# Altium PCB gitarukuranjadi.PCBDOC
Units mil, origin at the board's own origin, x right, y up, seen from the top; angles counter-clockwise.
Board outline 9670 x 5425 mil, 2 copper layers (Top Layer, Bottom Layer); 62 components, 44 nets, 204 pads, 7 vias.
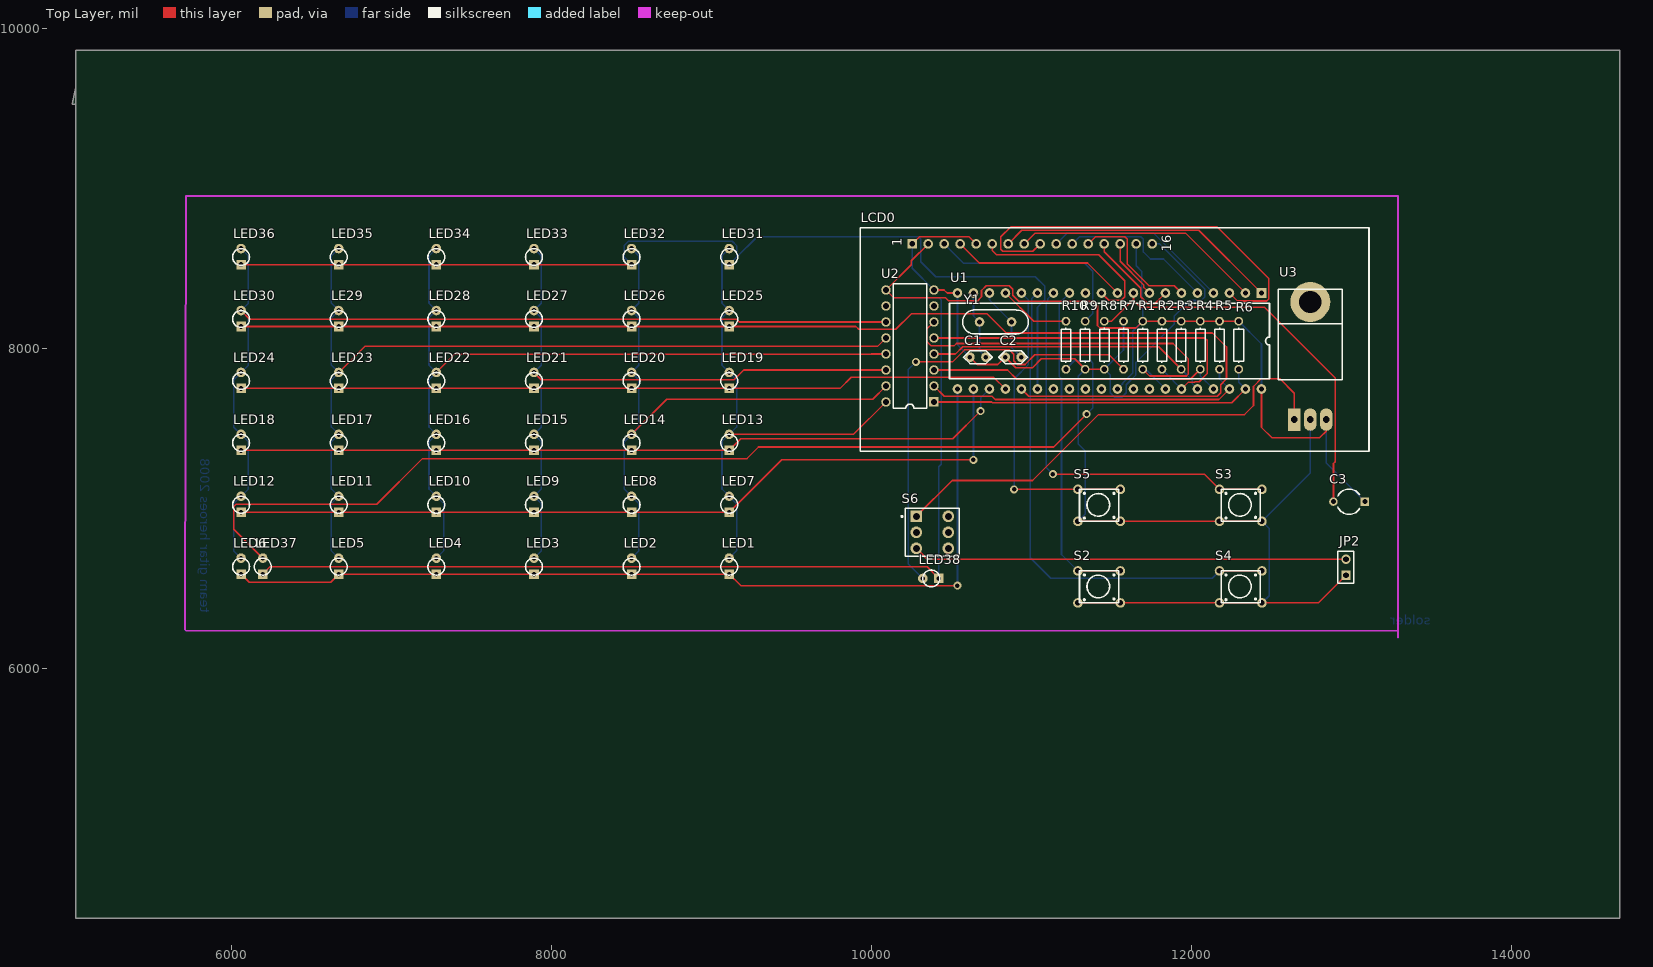
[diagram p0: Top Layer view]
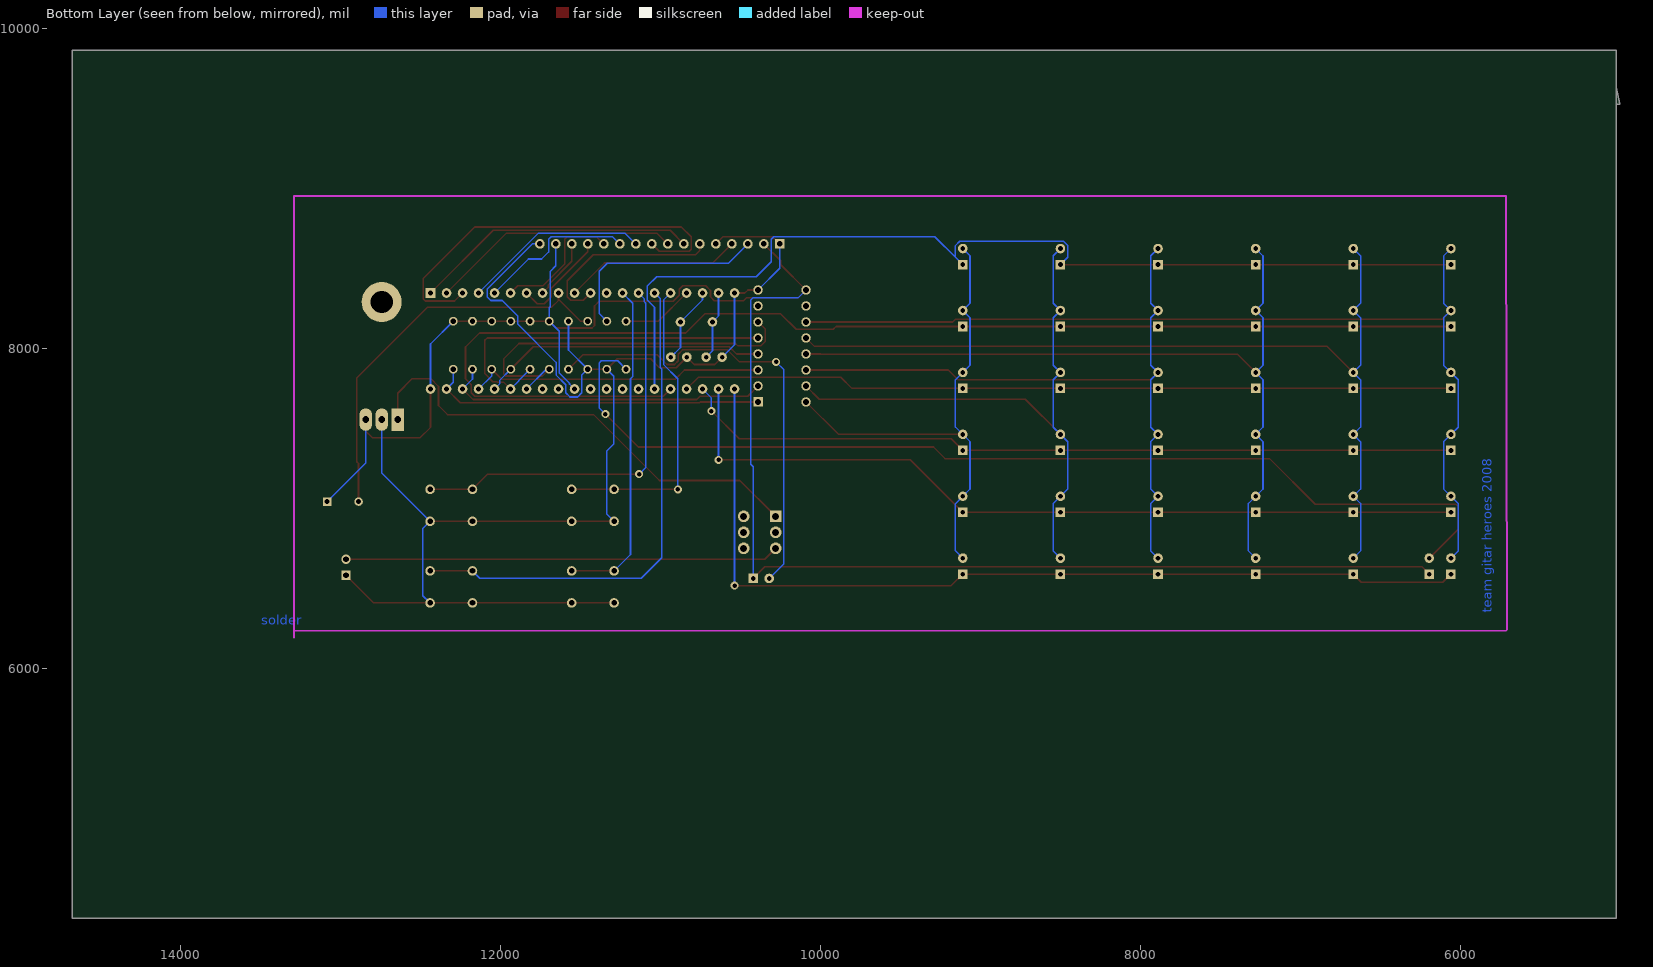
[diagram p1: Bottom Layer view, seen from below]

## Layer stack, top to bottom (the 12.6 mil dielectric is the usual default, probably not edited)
Top Layer: signal copper 1.4
Dielectric: dielectric 12.6, FR-4, Dk 4.8
Bottom Layer: signal copper 1.4

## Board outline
5025,9630 5025,4435 14675,4435 14675,9860 5025,9860 5025,9525 5005,9525

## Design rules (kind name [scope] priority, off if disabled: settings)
Clearance [All] p1: gap=10
ComponentClearance [All] p1: gap=10 collisioncheckmode=0
PolygonConnect [All] p1: connectstyle=Relief reliefconductorwidth=10 reliefentries=4 polygonreliefangle="90 Angle"
RoomDefinition gitarukuranjadi [InComponentClass('gitarukuranjadi')] p1: confinementstyle=ConfineIn formatcopy=TRUE outline 0,0 2000,0 2000,1000 0,1000
RoutingLayers [All] p1: top layer=Horizontal bottom layer=Vertical
RoutingVias [All] p1: holewidth=28 width=50 viastyle="Through Hole" minholewidth=28 minwidth=50 maxholewidth=28 maxwidth=50
SolderMaskExpansion [All] p1: expansion=4
TestPointUsage [All] p1: valid=0 allowmultiple=FALSE
Testpoint [All] p1: side=15 testpointundercomponent=TRUE minsize=40 maxsize=100 preferedsize=60 minholesize=0 maxholesize=40 preferedholesize=32 testpointgrid=1 style=1023 order=1234567890
Width [All] p1: maxlimit=10 minlimit=10 preferedwidth=10
16 further rules are at their usual default settings.

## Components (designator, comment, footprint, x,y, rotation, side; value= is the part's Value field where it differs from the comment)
C1 "cap 33pF" "cap 22/33uF" 11014.63,7942.72 r180 top
C2 "cap 33pF" "cap 22/33uF" 11234.63,7942.72 r180 top
C3 "Cap2" CAPR5-4X5 12985.02,7039.84 r180 top
JP2 "Header 2" HDR1X2 12965.02,6579.84 r90 top
LCD0 "LCD 16X2" "LCD 16X2" 12854.63,10807.72 r90 top
LE29 "LED kecil" "LED kecil" 6569.39,8234.27 r90 top
LED1 "LED kecil" "LED kecil" 9010.08,6686.3 r90 top
LED2 "LED kecil" "LED kecil" 8399.91,6686.3 r90 top
LED3 "LED kecil" "LED kecil" 7789.73,6686.3 r90 top
LED4 "LED kecil" "LED kecil" 7179.56,6686.3 r90 top
LED5 "LED kecil" "LED kecil" 6569.39,6686.3 r90 top
LED6 "LED kecil" "LED kecil" 5959.21,6686.3 r90 top
LED7 "LED kecil" "LED kecil" 9010.08,7073.29 r90 top
LED8 "LED kecil" "LED kecil" 8399.91,7073.29 r90 top
LED9 "LED kecil" "LED kecil" 7789.73,7073.29 r90 top
LED10 "LED kecil" "LED kecil" 7179.56,7073.29 r90 top
LED11 "LED kecil" "LED kecil" 6569.39,7073.29 r90 top
LED12 "LED kecil" "LED kecil" 5959.21,7073.29 r90 top
LED13 "LED kecil" "LED kecil" 9010.08,7460.28 r90 top
LED14 "LED kecil" "LED kecil" 8399.91,7460.28 r90 top
LED15 "LED kecil" "LED kecil" 7789.73,7460.28 r90 top
LED16 "LED kecil" "LED kecil" 7179.56,7460.28 r90 top
LED17 "LED kecil" "LED kecil" 6569.39,7460.28 r90 top
LED18 "LED kecil" "LED kecil" 5959.21,7460.28 r90 top
LED19 "LED kecil" "LED kecil" 9010.08,7847.28 r90 top
LED20 "LED kecil" "LED kecil" 8399.91,7847.28 r90 top
LED21 "LED kecil" "LED kecil" 7789.73,7847.28 r90 top
LED22 "LED kecil" "LED kecil" 7179.56,7847.28 r90 top
LED23 "LED kecil" "LED kecil" 6569.39,7847.28 r90 top
LED24 "LED kecil" "LED kecil" 5959.21,7847.28 r90 top
LED25 "LED kecil" "LED kecil" 9010.08,8234.27 r90 top
LED26 "LED kecil" "LED kecil" 8399.91,8234.27 r90 top
LED27 "LED kecil" "LED kecil" 7789.73,8234.27 r90 top
LED28 "LED kecil" "LED kecil" 7179.56,8234.27 r90 top
LED30 "LED kecil" "LED kecil" 5959.21,8234.27 r90 top
LED31 "LED kecil" "LED kecil" 9010.08,8621.26 r90 top
LED32 "LED kecil" "LED kecil" 8399.91,8621.26 r90 top
LED33 "LED kecil" "LED kecil" 7789.73,8621.26 r90 top
LED34 "LED kecil" "LED kecil" 7179.56,8621.26 r90 top
LED35 "LED kecil" "LED kecil" 6569.39,8621.26 r90 top
LED36 "LED kecil" "LED kecil" 5959.21,8621.26 r90 top
LED37 "LED kecil" "LED kecil" 6094.89,6686.3 r90 top
LED38 "LED kecil" "LED kecil" 10320,6460 r180 top
R1 "Res1" AXIAL-0.3 11694.63,8017.72 r270 top
R2 "Res1" AXIAL-0.3 11814.63,8017.72 r270 top
R3 "Res1" AXIAL-0.3 11934.63,8017.72 r270 top
R4 "Res1" AXIAL-0.3 12054.63,8017.72 r270 top
R5 "Res1" AXIAL-0.3 12174.63,8017.72 r270 top
R6 "Res1" AXIAL-0.3 12294.63,8017.72 r270 top
R7 "Res1" AXIAL-0.3 11574.63,8017.72 r270 top
R8 "Res1" AXIAL-0.3 11454.63,8017.72 r270 top
R9 "Res1" AXIAL-0.3 11334.63,8017.72 r270 top
R10 "Res1" AXIAL-0.3 11214.63,8017.72 r270 top
S2 "pushbutton" pushbutton 11854.63,6507.72 r0 top
S3 "pushbutton" pushbutton 12739.63,7017.72 r0 top
S4 "pushbutton" pushbutton 12739.63,6507.72 r0 top
S5 "pushbutton" pushbutton 11854.63,7017.72 r0 top
S6 "SW-DPDT" DPDT-6 10379.63,6847.72 r0 top
U1 "8051" "8051 40 pin" 10734.63,6597.72 r270 top
U2 "ULN2003A" A16 10239.63,8012.72 r90 top
U3 "7805" 78XX/79XX 12259.63,7792.72 r90 top
Y1 "XTAL" XTAL 10774.63,8062.72 r0 top

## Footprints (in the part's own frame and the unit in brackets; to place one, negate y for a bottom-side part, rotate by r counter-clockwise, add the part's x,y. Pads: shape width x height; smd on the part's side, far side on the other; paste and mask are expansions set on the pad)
78XX/79XX [mil]
  round 250 hole 140: 0(495,-482)
  rect 140x80 hole 42: 1(-240,-382)
  oval 140x80 hole 42: 2(-240,-482) 3(-240,-582)
  silkscreen extent 10,-682 575,-282
"8051 40 pin" [mil]
  rect 60x60 hole 33: 1(-1746,1702)
  round 60 hole 33: 2(-1746,1602) 3(-1746,1502) 4(-1746,1402) 5(-1746,1302) 6(-1746,1202) 7(-1746,1102) 8(-1746,1002) 9(-1746,902) 10(-1746,802) 11(-1746,702) 12(-1746,602) 13(-1746,502) 14(-1746,402) 15(-1746,302) 16(-1746,202) 17(-1746,102) 18(-1746,2) 19(-1746,-98) 20(-1746,-198) 21(-1146,-198) 22(-1146,-98) 23(-1146,2) 24(-1146,102) 25(-1146,202) 26(-1146,302) 27(-1146,402) 28(-1146,502) 29(-1146,602) 30(-1146,702) 31(-1146,802) 32(-1146,902) 33(-1146,1002) 34(-1146,1102) 35(-1146,1202) 36(-1146,1302) 37(-1146,1402) 38(-1146,1502) 39(-1146,1602) 40(-1146,1702)
  silkscreen extent -1681,-248 -1211,1752
A16 [mm] "DIP; 16 Leads; Row Spacing 7.62 mm; Pitch 2.54 mm"
  rect 1.5x1.5 hole 0.9: 1(-8.89,-3.81)
  round 1.5 hole 0.9: 2(-6.35,-3.81) 3(-3.81,-3.81) 4(-1.27,-3.81) 5(1.27,-3.81) 6(3.81,-3.81) 7(6.35,-3.81) 8(8.89,-3.81) 9(8.89,3.81) 10(6.35,3.81) 11(3.81,3.81) 12(1.27,3.81) 13(-1.27,3.81) 14(-3.81,3.81) 15(-6.35,3.81) 16(-8.89,3.81)
  silkscreen extent -9.85,-2.65 9.85,2.65
AXIAL-0.3 [mm]
  round 1.4 hole 0.85: 1(-3.81,0) 2(3.81,0)
  silkscreen extent -2.77,-0.76 2.77,0.76
"cap 22/33uF" [mil]
  round 60 hole 28: 1(300,0) 2(400,0)
  silkscreen extent 260,-40 440,40
CAPR5-4X5 [mm]
  rect 1.35x1.35 hole 0.8: 1(-2.5,0)
  round 1.35 hole 0.8: 2(2.5,0)
  silkscreen extent -1.69,-2 1.82,2
DPDT-6 [mm]
  rect 1.85x1.85 hole 1.1: 1(-2.54,2.54)
  round 1.85 hole 1.1: 2(-2.54,0) 3(-2.54,-2.54) 4(2.54,-2.54) 5(2.54,0) 6(2.54,2.54)
  silkscreen extent -4.96,-3.81 4.28,3.81
HDR1X2 [mm] "Connector; Header; 2 Position"
  rect 1.5x1.5 hole 0.9: 1(0,0)
  round 1.5 hole 0.9: 2(2.54,0)
  silkscreen extent -1.27,-1.27 3.81,1.27
"LCD 16X2" [mil]
  rect 60x60 hole 35: 1(-2157,2601)
  round 60 hole 35: 2(-2157,2501) 3(-2157,2401) 4(-2157,2301) 5(-2157,2201) 6(-2157,2101) 7(-2157,2001) 8(-2157,1901) 9(-2157,1801) 10(-2157,1701) 11(-2157,1601) 12(-2157,1501) 13(-2157,1401) 14(-2157,1301) 15(-2157,1201) 16(-2157,1101)
  silkscreen extent -3452,-254 -2057,2926
"LED kecil" [mil]
  rect 60x60 hole 30: 1(-100,-100)
  round 60 hole 30: 2(0,-100)
  silkscreen extent -106,-153 0,-47
pushbutton [mil]
  round 60 hole 35: 1(-565,-101) 1(-300,-101) 2(-565,99) 2(-300,99)
  silkscreen extent -555,-101 -310,99
XTAL [mil]
  round 60 hole 30: 1(-100,100) 2(100,100)
  silkscreen extent -205,25 205,175

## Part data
C1 C2: library part "cap 22/33uF"
C3: "Capacitor"
JP2: "Header, 2-Pin"
R1 R2 R3 R4 R5 R6 R7 R8 R9 R10: "Resistor"
S6: "Double-Pole, Double-Throw Switch"
U1: library part "8051 40 pin"
U2: "High-Voltage, High-Current Darlington Array"
U3: library part 7805/7809/7812/7905/7909/7912

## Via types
v1: diameter 50, hole 28, Top Layer to Bottom Layer, 7 vias

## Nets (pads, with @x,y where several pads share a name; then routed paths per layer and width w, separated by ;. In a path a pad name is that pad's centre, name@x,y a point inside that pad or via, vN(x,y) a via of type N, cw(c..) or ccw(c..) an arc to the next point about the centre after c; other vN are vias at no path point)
10: LCD0.7 U1.1 | length 1780.8
  Top Layer w10: LCD0.7 10938.91,8736 12044.34,8736 U1.1
11: LCD0.8 U1.2 | length 1564.2
  Top Layer w10: LCD0.8 11018.91,8716 11964.34,8716 U1.2
12: LCD0.9 U1.3 | length 2579.7
  Top Layer w10: LCD0.9 11007.91,8605 10820,8605 10808,8617 10808,8695 10869,8756 12161,8756 12482,8435 12482,8306 12470,8294 12286.34,8294 U1.3
13: LCD0.10 U1.4 | length 1164.2
  Bottom Layer w10: LCD0.10 11218.91,8716 11764.34,8716 U1.4
14: LCD0.11 U1.5 | length 994.5
  Bottom Layer w10: LCD0.11 11298.91,8696 11683,8696 11699,8680 11699,8600 11743,8556 11824.34,8556 U1.5
15: LCD0.12 U1.6 | length 838.9
  Top Layer w10: LCD0.12 11398.91,8696 11583,8696 11599,8680 11599,8524.29 11734.29,8389 11891.34,8389 U1.6
16: LCD0.13 U1.7 | length 626.2
  Top Layer w10: LCD0.13 11453.63,8601.37 11682,8373 11682,8320 11726,8276 11768.91,8276 U1.7
17: LCD0.14 U1.8 | length 382.8
  Top Layer w10: LCD0.14 11553.63,8541.37 11702,8393 11702,8378.34 U1.8
30: LCD0.4 U1.10 | length 1110.2
  Top Layer w10: LCD0.4 10673.34,8531 11349.34,8531 U1.10
31: LCD0.6 U1.11 | length 1222.2
  Top Layer w10: LCD0.6 10753.63,8609.37 10780,8583 11420,8583 11582,8421 11582,8320 11560,8298 11482.34,8298 U1.11
32: U1.12
33: S2.2 U1.13 | length 2077.5
  Top Layer w10: S2.2@11289.63,6606.72 S2.2@11554.63,6606.72
  Bottom Layer w10: U1.13 11172,8279.09 11172,7822 11187,7807 11187,6709.34 S2.2@11289.63,6606.72
34: S3.2 U1.14 | length 2514.7
  Top Layer w10: v1(11133,7211) 12080.34,7211 12174.63,7116.72 S3.2@12439.63,7116.72
  Bottom Layer w10: v1(11133,7211) 11091,7253 11091,8279 11102,8290 11102,8309.09 U1.14
35: S4.2 U1.15 | length 3194.2
  Top Layer w10: S4.2@12174.63,6606.72 S4.2@12439.63,6606.72
  Bottom Layer w10: U1.15 11000,8307.09 11000,7878 10991,7869 10991,6689 11119,6561 12128.91,6561 S4.2@12174.63,6606.72
36: S5.2 U1.16 | length 1945.5
  Top Layer w10: v1(10891,7116.72) 11289.63,7116.72 S5.2@11554.63,7116.72
  Bottom Layer w10: v1(10891,7116.72) 10891,7808.37 10980,7897.37 10980,8300.34 U1.16
37: R10.1 U1.17 | length 450.9
  Top Layer w10: U1.17 11012.63,8167.72 R10.1
B1: R6.2 U1.39 U2.1 | length 2125.9
  Top Layer w10: U2.1 10752,7662.72 10756.72,7658 12250.91,7658 U1.39
  Bottom Layer w10: R6.2 12294.63,7785.72 U1.39
B2: R5.2 U1.38 U2.2 | length 2059
  Top Layer w10: U2.2 10454.34,7698 10752,7698 10772,7678 12170.91,7678 U1.38
  Bottom Layer w10: R5.2 12174.63,7805.72 U1.38
B3: R4.2 U1.37 U2.3 | length 1872.9
  Top Layer w10: U2.3 10850,7862.72 10907.72,7805 11991.91,7805 R4.2
  Bottom Layer w10: R4.2 12054.63,7825.72 U1.37
B4: R3.2 U1.36 U2.4 | length 1788.1
  Top Layer w10: U2.4 10523.72,7962.72 10569,8008 11794.34,8008 R3.2
  Bottom Layer w10: R3.2 12005,7797.34 12005,7775.34 U1.36
B5: R2.2 U1.35 U2.5 | length 2298.3
  Top Layer w10: U2.5 12083.28,8062.72 12098,8048 12098,7840 12047,7789 12021,7789 12017,7785 11977.91,7785 U1.35
  Bottom Layer w10: R2.2 11886,7796.34 11886,7794.34 U1.35
B6: R1.2 U1.34 U2.6 | length 2428.1
  Top Layer w10: U2.6 10345,8118.09 10345,8040 10372,8013 10515,8013 10530,8028 11884,8028 11978,7934 11978,7835 11968,7825 11737.34,7825 R1.2
  Bottom Layer w10: R1.2 11712.63,7867.72 U1.34
G1: LED1.2 LED7.2 LED13.2 LED19.2 LED25.2 LED31.2 U2.16 | length 3186.5
  Top Layer w10: LED13.2 9887.19,7460.28 U2.16
  Bottom Layer w10: LED1.2 9156,6732.22 9156,7027.37 LED7.2 9065,7118.37 9065,7415.21 LED13.2 9156,7506.21 9156,7801.35 LED19.2 9065,7892.35 9065,8189.19 LED25.2 9065,8279.35 9065,8576.18 LED31.2
G2: LED2.2 LED8.2 LED14.2 LED20.2 LED26.2 LED32.2 U2.15 | length 3837.4
  Top Layer w10: LED14.2 8719.62,7680 10006.91,7680 U2.15
  Bottom Layer w10: LED2.2 8545,6731.39 8545,7028.2 LED8.2 8454,7119.2 8454,7414.38 LED14.2 8545,7505.38 8545,7802.18 LED20.2 8545,7892.37 8545,8189.17 LED26.2 8545,8279.36 8545,8576.17 LED32.2
G3: LED3.2 LED9.2 LED15.2 LED21.2 LED27.2 LED33.2 U2.14 | length 4366.3
  Top Layer w10: LED21.2 7935.01,7802 9140,7802 9200.72,7862.72 U2.14
  Bottom Layer w10: LED3.2 7935,6731.57 7935,7028.02 LED9.2 7935,7118.56 7935,7415.02 LED15.2 7935,7505.55 7935,7802.01 LED21.2 7935,7892.54 7935,8189 LED27.2 7935,8279.54 7935,8575.99 LED33.2
G4: LED4.2 LED10.2 LED16.2 LED22.2 LED28.2 LED34.2 U2.13 | length 4981.5
  Top Layer w10: LED22.2 7394.28,7962 9997.28,7962 9998,7962.72 U2.13
  Bottom Layer w10: LED4.2 7325,6731.74 7325,7027.85 LED10.2 7234,7118.85 7234,7414.73 LED16.2 7234,7505.84 7234,7801.72 LED22.2 7234,7892.83 7234,8188.71 LED28.2 7234,8279.83 7234,8575.7 LED34.2
G5: LE29.2 LED5.2 LED11.2 LED17.2 LED23.2 LED35.2 U2.12 | length 5632.4
  Top Layer w10: LED23.2 6832.11,8010 10036.91,8010 U2.12
  Bottom Layer w10: LED5.2 6624,6731.69 6624,7027.91 LED11.2 6624,7118.68 6624,7414.9 LED17.2 6624,7505.67 6624,7801.89 LED23.2 6624,7892.66 6624,8188.88 LE29.2 6624,8279.65 6624,8575.87 LED35.2
G6: LED6.2 LED12.2 LED18.2 LED24.2 LED30.2 LED36.2 U2.11 | length 6183.7
  Top Layer w10: LED30.2 6113.48,8180 9156,8180 9173.28,8162.72 U2.11
  Bottom Layer w10: LED6.2 6014,6731.51 6014,7028.08 LED12.2 6105,7119.08 6105,7414.5 LED18.2 6014,7505.5 6014,7802.06 LED24.2 6105,7893.06 6105,8188.48 LED30.2 6105,8280.06 6105,8575.47 LED36.2
GND: C1.2 C2.2 JP2.1 LCD0.1 LCD0.5 LCD0.16 R7.1 R8.2 R9.2 S2.1 S3.1 S4.1 S5.1 U1.20 U2.8 U3.2 | length 9510.3
  Top Layer w10: LCD0.1 10298.91,8696 10608.34,8696 LCD0.5 ; U2.8 10453,8362.72 10472,8343.72 U1.20 ; C1.2 10660.34,7897 10788.91,7897 C2.2 10900.34,7877 11005,7877 11061,7933 11269.34,7933 R9.2 R8.2 ; S2.1@11289.63,6406.72 11554.63,6406.72 12174.63,6406.72 12439.63,6406.72 12791.89,6406.72 JP2.1 ; S5.1@11289.63,6916.72 11554.63,6916.72 12174.63,6916.72 S3.1@12439.63,6916.72
  Bottom Layer w10: LCD0.1 10253.63,8498.72 U2.8 ; U1.20 10536.63,8020.72 C1.2 ; S5.1@11289.63,6916.72 11335,6962.09 11335,7356 11291,7400 11291,7824.09 R9.2 ; R7.1 11574.63,7987.72 R8.2 11491,7831.34 11491,7720 11517,7694 11565,7694 11591,7720 11591,7770 11652,7831 11652,7909.93 11892,8149.93 11892,8200 11989,8297 12060,8297 12082,8319 12082,8369 11800.28,8650.72 LCD0.16 ; S4.1@12439.63,6406.72 12485,6452.09 12485,6871.34 12439.63,6916.72 12741.63,7218.72 U3.2
NetC1_1: C1.1 U1.19 Y1.1 | length 433.3
  Bottom Layer w10: U1.19 10636.63,8200.72 Y1.1 10674.63,7982.72 C1.1
NetC2_1: C2.1 U1.18 Y1.2 | length 483
  Bottom Layer w10: U1.18 10736.63,8300.72 Y1.2 10874.63,8002.72 C2.1
NetC3_2: C3.2 R8.1 U1.9 | length 2522.8
  Top Layer w10: R8.1 11500,8167.72 11636.63,8304.34 ; U1.9 11636.63,8304.34 ; C3.2 12886.59,7278.59 12897,7289 12897,7812 12455,8254 11680,8254 11636.63,8297.37 11636.63,8304.34
NetJP2_2: JP2.2 S6.3 | length 2713.5
  Top Layer w10: S6.3 10347.5,6679.84 JP2.2
NetLCD0_3: LCD0.3 R9.1 | length 1331
  Bottom Layer w10: LCD0.3 10574.34,8530 11332,8530 11382,8480 11382,8215.09 R9.1
NetLED37_2: LED37.2 R10.2 | length 6497.7
  Top Layer w10: LED37.2 6014,6867.19 6014,7010 6027,7023 6907,7023 7193,7309 9221,7309 9293,7381 11138,7381 v1(11344,7587)
  Bottom Layer w10: R10.2 11266.91,7920 11368.91,7920 11382,7906.91 11382,7625 v1(11344,7587)
NetLED38_2: LED38.2 R7.2 | length 2864.3
  Top Layer w10: v1(10277,7913) 10505.28,7913 10580.28,7988 10861.63,7988 10889,7960.63 10889,7920 10912,7897 10959.28,7897 11020.28,7958 11484.34,7958 R7.2
  Bottom Layer w10: v1(10277,7913) 10228,7864 10228,6652 LED38.2
NetS6_1: S6.1 U3.1 | length 2990
  Top Layer w10: S6.1 10503.91,7172 11006,7172 11418,7584 12331,7584 12387,7640 12387,7760 12434,7807 12552,7807 12641.63,7717.37 U3.1
R1: LED1.1 LED2.1 LED3.1 LED4.1 LED5.1 LED6.1 U1.21 | length 5777.3
  Top Layer w10: LED6.1 6109.51,6536 6619.09,6536 LED5.1 LED4.1 LED3.1 LED2.1 LED1.1 9181.38,6515 v1(10536.63,6515)
  Bottom Layer w10: v1(10536.63,6515) U1.21
R2: LED7.1 LED8.1 LED9.1 LED10.1 LED11.1 LED12.1 U1.22 | length 5155.9
  Top Layer w10: LED12.1 LED11.1 LED10.1 LED9.1 LED8.1 LED7.1 9437.79,7301 v1(10636.63,7301)
  Bottom Layer w10: v1(10636.63,7301) U1.22
R3: LED13.1 LED14.1 LED15.1 LED16.1 LED17.1 LED18.1 U1.23 | length 4884.3
  Top Layer w10: LED18.1 LED17.1 LED16.1 LED15.1 LED14.1 LED13.1 9182.79,7433 10508,7433 v1(10681,7606)
  Bottom Layer w10: v1(10681,7606) 10681,7688.09 U1.23
R4: LED19.1 LED20.1 LED21.1 LED22.1 LED23.1 LED24.1 U1.24 | length 4837.5
  Top Layer w10: LED24.1 LED23.1 LED22.1 LED21.1 LED20.1 LED19.1 9802.28,7747.28 9873,7818 10762.34,7818 U1.24
R5: LE29.1 LED25.1 LED26.1 LED27.1 LED28.1 LED30.1 U1.25 | length 7865.8
  Top Layer w10: LED30.1 LE29.1 LED28.1 LED27.1 LED26.1 LED25.1 9902,8134.27 9919.27,8117 10151,8117 10247,8213 10722,8213 10841,8094 12130,8094 12218,8006 12218,7807 12182,7771 12182,7720 12160,7698 10982.34,7698 U1.25
R6: LED31.1 LED32.1 LED33.1 LED34.1 LED35.1 LED36.1 U1.26 | length 6293.2
  Top Layer w10: LED36.1 LED35.1 LED34.1 LED33.1 LED32.1
  Bottom Layer w10: LED32.1 8454,8567.17 8454,8641 8480,8667 9129,8667 9156,8640 9156,8567.18 ; LED31.1 9156,8567.18 ; U1.26 11036.63,8254 11082,8299.37 11082,8387 11023,8446 10401,8446 10308,8539 10308,8680 10292,8696 9284.82,8696 9156,8567.18
VCC: C3.1 LCD0.2 LCD0.15 LED37.1 LED38.1 R1.1 R2.1 R3.1 R4.1 R5.1 R6.1 U1.31 U1.40 U2.9 U3.3 | length 12150.1
  Top Layer w10: LED37.1 6240.59,6632 10348,6632 LED38.1 ; LCD0.2 10248,8545.09 10248,8521.09 U2.9 10139.34,8313 10463,8313 10480,8296 10663,8296 10687,8320 10687,8360 10716,8389 10860,8389 10882,8367 10882,8330 10920,8292 11383,8292 11412,8263 11412,8140 11427,8125 11651.91,8125 R1.1 R2.1 R3.1 R4.1 R5.1 R6.1 ; U1.40 12436.63,7503.75 12500.37,7440 12801.63,7440 12841.63,7480 U3.3
  Bottom Layer w10: U2.9 10139.34,8313 10422,8313 10435,8300 10435,7273 10420,7258 LED38.1 ; U1.31 11568,7775.09 11568,7780 11632,7844 11632,8105.09 R1.1 11694.63,8252.37 11689,8258 11689,8478.63 11653.63,8514 LCD0.15 ; R6.1 12436.63,8025.72 U1.40 ; U3.3 12841.63,7281.66 C3.1
pads on no net: S6.2 S6.4 S6.5 S6.6 U1.27 U1.28 U1.29 U1.30 U1.32 U1.33 U2.7 U2.10 U3.0

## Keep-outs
Keep-Out Layer:
  lines w10: 5708.66,6240.16 5715,8950 13290.04,8950 13290.04,6190 ; 5715,6233.46 13290.04,6233.46

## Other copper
Bottom Layer:
  text "team gitar heroes 2008" at 5805,6345 h60 r270
  text "solder" at 13495,6270 h60

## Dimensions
6062.99,8562.99 to 6692.91,8562.99 on Top Layer
6043.31,8169.29 to 6043.31,8562.99 on Top Layer
6051.45,8582.68 to 9122.32,8523.62 on Top Layer
5964.57,8562.99 to 6122.05,6633.86 on Top Layer
5669.29,8945.15 to 5708.66,6228.62 on Top Layer
5711.5,8799.21 to 13309.93,8996.06 on Top Layer
5944.88,8950.15 to 5984.25,8556.45 on Top Layer
12903.39,8759.84 to 12903.39,8956.69 on Top Layer
13098.41,8707.24 to 13295.26,8707.24 on Top Layer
